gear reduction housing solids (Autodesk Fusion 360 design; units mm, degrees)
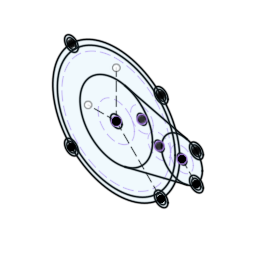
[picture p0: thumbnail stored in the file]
parameter "Drive_Gear_Dia" = 96 (= "( ( Drive_Gear_Teeth * Gear_Module ) * 1 mm )")
parameter "Driven_Gear_Dia" = 32 (= "( ( Driven_Gear_Teeth * Gear_Module ) * 1 mm )")
parameter "Idle_Gear_Dia" = 20 (= "( ( Idle_Gear_Teeth * Gear_Module ) * 1 mm )")
parameter "Mount_Bolts" = 8
parameter "Idle_Gear_Shaft" = 8
parameter "Mount_Bolt_Flange" = 12
parameter "Gear_Clearance_Dia" = 8
parameter "Gear_Thickness" = 8
parameter "Idle_Gear_Thickness" = 21
parameter "Housing_Wall_Thickness" = 3
parameter "Gear_Gap" = 5
sketch "Layout Sketch" plane through (0, 0, 0) normal (0, 0, 1) x axis (1, 0, 0)
  circle C1 centre (0, 0) radius 48
  circle C2 centre (0, 0) radius 16
  circle C3 centre (22.6316, 12.7989) radius 10
  circle C4 centre (38, 0) radius 10
  circle C5 centre (58, 0) radius 10
  point P1 (0, 0)
  point P2 (0, 0)
  point P3 (0, 0)
  point P6 (58, 0)
  point P5 (38, 0)
  coincident P1 P2
  concentric C1 C2
  horizontal P3 P6
  tangent C2 C3
  tangent C3 C4
  tangent C1 C5
  tangent C1 C4
  horizontal P3 P5
  dimension "d15" diameter C1 = 96 (= "Drive_Gear_Dia")
  dimension "d16" diameter C2 = 32 (= "Driven_Gear_Dia")
  dimension "d17" diameter C3 = 20 (= "Idle_Gear_Dia")
  dimension "d18" diameter C5 = 20 (= "Idle_Gear_Dia")
  dimension "d19" diameter C4 = 20 (= "Idle_Gear_Dia")
sketch "Housing Layout Sketch" plane through (0, 0, 0) normal (0, 0, 1) x axis (1, 0, 0)
  line L1 (62.3448, 17.4678) -> (7.7241, 31.0538)
  line L2 (7.7241, -31.0538) -> (62.3448, -17.4678)
  line L3 (39.598, -39.598) -> (0, 0)
  line L4 (70.7279, -12.7279) -> (58, 0)
  line L5 (0, 40.8023) -> (0, 0)
  line L6 (-24.8762, 0) -> (0, 0)
  circle C1 centre (0, 0) radius 48
  circle C2 centre (0, 0) radius 16
  circle C3 centre (22.6316, 12.7989) radius 10
  circle C4 centre (38, 0) radius 10
  circle C5 centre (58, 0) radius 10
  circle C6 centre (0, 0) radius 52
  circle C7 centre (0, 0) radius 56
  circle C8 centre (0, 0) radius 32
  circle C9 centre (58, 0) radius 18
  circle C10 centre (0, 0) radius 5
  circle C11 centre (22.6316, 12.7989) radius 4
  circle C12 centre (38, 0) radius 4
  circle C13 centre (58, 0) radius 4
  circle C14 centre (39.598, -39.598) radius 6
  circle C15 centre (39.598, -39.598) radius 4
  circle C16 centre (70.7279, -12.7279) radius 6
  circle C17 centre (70.7279, -12.7279) radius 4
  circle C18 centre (-39.598, -39.598) radius 6
  circle C19 centre (-39.598, -39.598) radius 4
  circle C20 centre (-39.598, 39.598) radius 4
  circle C21 centre (-39.598, 39.598) radius 6
  circle C22 centre (39.598, 39.598) radius 4
  circle C23 centre (39.598, 39.598) radius 6
  circle C24 centre (70.7279, 12.7279) radius 4
  circle C25 centre (70.7279, 12.7279) radius 6
  point P11 (7.7241, 31.0538)
  point P12 (62.3448, 17.4678)
  point P13 (62.3448, -17.4678)
  point P14 (7.7241, -31.0538)
  point P19 (39.598, -39.598)
  point P21 (70.7279, -12.7279)
  point P15 (0, 0)
  point P23 (0, 0)
  point P20 (39.598, -39.598)
  point P24 (39.598, -39.598)
  point P18 (58, 0)
  point P25 (58, 0)
  point P26 (70.7279, -12.7279)
  point P8 (0, 0)
  point P27 (0, 0)
  point P29 (-39.598, -39.598)
  point P3 (0, 0)
  point P31 (0, 0)
  concentric C2 C6
  concentric C6 C7
  concentric C6 C8
  concentric C5 C9
  coincident C8 P11
  coincident C9 P12
  coincident C9 P13
  coincident C8 P14
  tangent C8 L1
  tangent C9 L1
  tangent C9 L2
  tangent C8 L2
  concentric C1 C10
  concentric C3 C11
  concentric C4 C12
  concentric C5 C13
  coincident C7 P19
  concentric C14 C15
  coincident C9 P21
  concentric C16 C17
  coincident P15 P23
  coincident P20 P24
  coincident P18 P25
  coincident P21 P26
  coincident P8 P27
  vertical L5
  coincident C7 P29
  concentric C18 C19
  symmetric C14 L5 C18
  symmetric C15 L5 C19
  coincident P3 P31
  horizontal L6
  symmetric C14 L6 C23
  symmetric C15 L6 C22
  symmetric C16 L6 C25
  symmetric C17 L6 C24
  symmetric C18 L6 C21
  symmetric C19 L6 C20
  dimension "d21" distance C1 C7 = 8 (= "Gear_Clearance_Dia")
  dimension "d22" distance C5 C9 = 8 (= "Gear_Clearance_Dia")
  dimension "d23" distance C2 C8 = 16 (= "Gear_Clearance_Dia * 2")
  dimension "d24" diameter C10 = 10
  dimension "d25" diameter C11 = 8 (= "Idle_Gear_Shaft")
  dimension "d26" diameter C12 = 8 (= "Idle_Gear_Shaft")
  dimension "d27" diameter C13 = 8 (= "Idle_Gear_Shaft")
  dimension "d28" angle L3 L5 = 45
  dimension "d29" angle L4 L5 = 45 (= "d28")
  dimension "d30" diameter C15 = 8 (= "Mount_Bolts")
  dimension "d31" diameter C17 = 8 (= "Mount_Bolts")
  dimension "d32" distance C14 C15 = 2
  dimension "d33" distance C16 C17 = 2 (= "d32")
